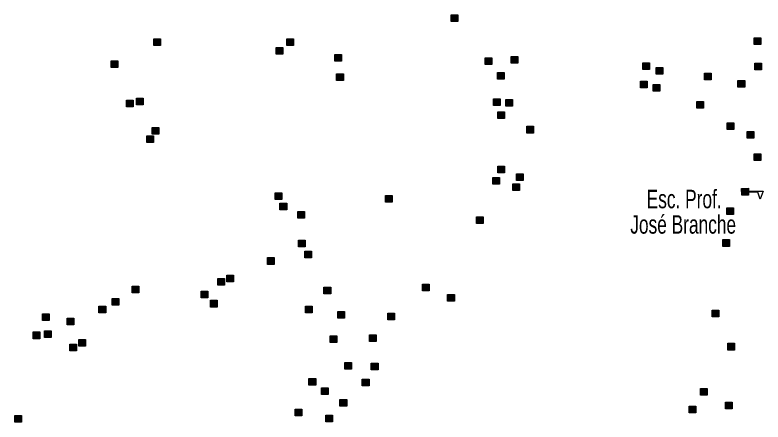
# Model space of a CAD drawing. Extents: x 649.2 to 674.4, y 7040 to 7068.1.
# Drawn here: x 670.821 to 674.06, y 7041.775 to 7043.538 of the extents above; entities that cross this region are included whole.
import ezdxf
from ezdxf.enums import TextEntityAlignment as Align

# ---------------------------------------------------------------- set-up
doc = ezdxf.new("R2010")
doc.units = 0
doc.header["$LTSCALE"] = 0.032
doc.layers.add('2', color=7, linetype='Continuous', lineweight=25)
doc.layers.add('4', color=7, linetype='Continuous', lineweight=25)
doc.layers.add('61', color=7, linetype='Continuous')

msp = doc.modelspace()

# ---------------------------------------------------------------- hatches: boundary and pattern name
at = {"layer": '2'}
for points in [[(672.7097, 7043.5383), (672.7387, 7043.5383), (672.7387, 7043.5093), (672.7097, 7043.5093)], [(671.4226, 7043.4348), (671.4516, 7043.4348), (671.4516, 7043.4058), (671.4226, 7043.4058)], [(671.9981, 7043.435), (672.0271, 7043.435), (672.0271, 7043.406), (671.9981, 7043.406)], [(674.0212, 7043.4393), (674.0502, 7043.4393), (674.0502, 7043.4103), (674.0212, 7043.4103)], [(671.9518, 7043.398), (671.9808, 7043.398), (671.9808, 7043.369), (671.9518, 7043.369)], [(671.2371, 7043.3401), (671.2661, 7043.3401), (671.2661, 7043.3111), (671.2371, 7043.3111)], [(672.2062, 7043.3664), (672.2352, 7043.3664), (672.2352, 7043.3374), (672.2062, 7043.3374)], [(672.8572, 7043.3529), (672.8862, 7043.3529), (672.8862, 7043.3239), (672.8572, 7043.3239)], [(672.9688, 7043.3579), (672.9978, 7043.3579), (672.9978, 7043.3289), (672.9688, 7043.3289)], [(673.5395, 7043.3313), (673.5685, 7043.3313), (673.5685, 7043.3023), (673.5395, 7043.3023)], [(673.5968, 7043.3104), (673.6258, 7043.3104), (673.6258, 7043.2814), (673.5968, 7043.2814)], [(674.0241, 7043.329), (674.0531, 7043.329), (674.0531, 7043.3), (674.0241, 7043.3)], [(672.2139, 7043.2832), (672.2429, 7043.2832), (672.2429, 7043.2542), (672.2139, 7043.2542)], [(672.91, 7043.2891), (672.939, 7043.2891), (672.939, 7043.2601), (672.91, 7043.2601)], [(673.8065, 7043.2867), (673.8355, 7043.2867), (673.8355, 7043.2577), (673.8065, 7043.2577)], [(673.5295, 7043.2513), (673.5585, 7043.2513), (673.5585, 7043.2223), (673.5295, 7043.2223)], [(673.9511, 7043.2538), (673.9801, 7043.2538), (673.9801, 7043.2248), (673.9511, 7043.2248)], [(673.5841, 7043.2376), (673.6131, 7043.2376), (673.6131, 7043.2086), (673.5841, 7043.2086)], [(671.3473, 7043.178), (671.3763, 7043.178), (671.3763, 7043.149), (671.3473, 7043.149)], [(672.8921, 7043.1755), (672.9211, 7043.1755), (672.9211, 7043.1465), (672.8921, 7043.1465)], [(671.3046, 7043.1689), (671.3336, 7043.1689), (671.3336, 7043.1399), (671.3046, 7043.1399)], [(672.9459, 7043.1725), (672.9749, 7043.1725), (672.9749, 7043.1435), (672.9459, 7043.1435)], [(673.7724, 7043.1639), (673.8014, 7043.1639), (673.8014, 7043.1349), (673.7724, 7043.1349)], [(672.912, 7043.1187), (672.941, 7043.1187), (672.941, 7043.0897), (672.912, 7043.0897)], [(671.4148, 7043.0509), (671.4438, 7043.0509), (671.4438, 7043.0219), (671.4148, 7043.0219)], [(673.0376, 7043.0559), (673.0666, 7043.0559), (673.0666, 7043.0269), (673.0376, 7043.0269)], [(673.9043, 7043.0711), (673.9333, 7043.0711), (673.9333, 7043.0421), (673.9043, 7043.0421)], [(671.3927, 7043.0146), (671.4217, 7043.0146), (671.4217, 7042.9856), (671.3927, 7042.9856)], [(673.9908, 7043.0338), (674.0198, 7043.0338), (674.0198, 7043.0048), (673.9908, 7043.0048)], [(674.0208, 7042.9365), (674.0498, 7042.9365), (674.0498, 7042.9075), (674.0208, 7042.9075)], [(672.9115, 7042.8828), (672.9405, 7042.8828), (672.9405, 7042.8538), (672.9115, 7042.8538)], [(672.9917, 7042.8495), (673.0207, 7042.8495), (673.0207, 7042.8205), (672.9917, 7042.8205)], [(672.89, 7042.8344), (672.919, 7042.8344), (672.919, 7042.8054), (672.89, 7042.8054)], [(672.9766, 7042.8066), (673.0056, 7042.8066), (673.0056, 7042.7776), (672.9766, 7042.7776)], [(671.9474, 7042.7676), (671.9764, 7042.7676), (671.9764, 7042.7386), (671.9474, 7042.7386)], [(672.4252, 7042.7569), (672.4542, 7042.7569), (672.4542, 7042.7279), (672.4252, 7042.7279)], [(671.9685, 7042.7229), (671.9975, 7042.7229), (671.9975, 7042.6939), (671.9685, 7042.6939)], [(672.0456, 7042.6873), (672.0746, 7042.6873), (672.0746, 7042.6583), (672.0456, 7042.6583)], [(673.9027, 7042.7025), (673.9317, 7042.7025), (673.9317, 7042.6735), (673.9027, 7042.6735)], [(672.8194, 7042.6637), (672.8484, 7042.6637), (672.8484, 7042.6347), (672.8194, 7042.6347)], [(672.048, 7042.5631), (672.077, 7042.5631), (672.077, 7042.5341), (672.048, 7042.5341)], [(673.8853, 7042.5649), (673.9143, 7042.5649), (673.9143, 7042.5359), (673.8853, 7042.5359)], [(672.0764, 7042.5153), (672.1054, 7042.5153), (672.1054, 7042.4863), (672.0764, 7042.4863)], [(671.914, 7042.487), (671.943, 7042.487), (671.943, 7042.458), (671.914, 7042.458)], [(671.6992, 7042.3964), (671.7282, 7042.3964), (671.7282, 7042.3674), (671.6992, 7042.3674)], [(671.7381, 7042.4105), (671.7671, 7042.4105), (671.7671, 7042.3815), (671.7381, 7042.3815)], [(671.328, 7042.3635), (671.357, 7042.3635), (671.357, 7042.3345), (671.328, 7042.3345)], [(672.5856, 7042.3716), (672.6146, 7042.3716), (672.6146, 7042.3426), (672.5856, 7042.3426)], [(671.6278, 7042.3416), (671.6568, 7042.3416), (671.6568, 7042.3126), (671.6278, 7042.3126)], [(672.159, 7042.3585), (672.188, 7042.3585), (672.188, 7042.3295), (672.159, 7042.3295)], [(671.2422, 7042.3095), (671.2712, 7042.3095), (671.2712, 7042.2805), (671.2422, 7042.2805)], [(671.6673, 7042.3021), (671.6963, 7042.3021), (671.6963, 7042.2731), (671.6673, 7042.2731)], [(672.6944, 7042.327), (672.7234, 7042.327), (672.7234, 7042.298), (672.6944, 7042.298)], [(671.185, 7042.2768), (671.214, 7042.2768), (671.214, 7042.2478), (671.185, 7042.2478)], [(672.0785, 7042.2772), (672.1075, 7042.2772), (672.1075, 7042.2482), (672.0785, 7042.2482)], [(670.9406, 7042.2442), (670.9696, 7042.2442), (670.9696, 7042.2152), (670.9406, 7042.2152)], [(672.2183, 7042.2537), (672.2473, 7042.2537), (672.2473, 7042.2247), (672.2183, 7042.2247)], [(672.4353, 7042.2463), (672.4643, 7042.2463), (672.4643, 7042.2173), (672.4353, 7042.2173)], [(673.839, 7042.2592), (673.868, 7042.2592), (673.868, 7042.2302), (673.839, 7042.2302)], [(671.0469, 7042.2254), (671.0759, 7042.2254), (671.0759, 7042.1964), (671.0469, 7042.1964)], [(670.9488, 7042.1698), (670.9778, 7042.1698), (670.9778, 7042.1408), (670.9488, 7042.1408)], [(670.9006, 7042.1649), (670.9296, 7042.1649), (670.9296, 7042.1359), (670.9006, 7042.1359)], [(672.1859, 7042.1489), (672.2149, 7042.1489), (672.2149, 7042.1199), (672.1859, 7042.1199)], [(672.3565, 7042.1526), (672.3855, 7042.1526), (672.3855, 7042.1236), (672.3565, 7042.1236)], [(671.0583, 7042.1118), (671.0873, 7042.1118), (671.0873, 7042.0828), (671.0583, 7042.0828)], [(671.0975, 7042.133), (671.1265, 7042.133), (671.1265, 7042.104), (671.0975, 7042.104)], [(673.9074, 7042.1159), (673.9364, 7042.1159), (673.9364, 7042.0869), (673.9074, 7042.0869)], [(672.2498, 7042.033), (672.2788, 7042.033), (672.2788, 7042.004), (672.2498, 7042.004)], [(672.3639, 7042.0293), (672.3929, 7042.0293), (672.3929, 7042.0003), (672.3639, 7042.0003)], [(672.0941, 7041.9635), (672.1231, 7041.9635), (672.1231, 7041.9345), (672.0941, 7041.9345)], [(672.3249, 7041.9607), (672.3539, 7041.9607), (672.3539, 7041.9317), (672.3249, 7041.9317)], [(672.1478, 7041.9236), (672.1768, 7041.9236), (672.1768, 7041.8946), (672.1478, 7041.8946)], [(673.7883, 7041.9201), (673.8173, 7041.9201), (673.8173, 7041.8911), (673.7883, 7041.8911)], [(672.2282, 7041.8723), (672.2572, 7041.8723), (672.2572, 7041.8433), (672.2282, 7041.8433)], [(673.8968, 7041.8614), (673.9258, 7041.8614), (673.9258, 7041.8324), (673.8968, 7041.8324)], [(672.0347, 7041.8306), (672.0637, 7041.8306), (672.0637, 7041.8016), (672.0347, 7041.8016)], [(673.7395, 7041.8433), (673.7685, 7041.8433), (673.7685, 7041.8143), (673.7395, 7041.8143)], [(670.8213, 7041.8038), (670.8503, 7041.8038), (670.8503, 7041.7748), (670.8213, 7041.7748)], [(672.1674, 7041.8045), (672.1964, 7041.8045), (672.1964, 7041.7755), (672.1674, 7041.7755)]]:
    msp.add_hatch(color=256, dxfattribs=at).paths.add_polyline_path(points)
at = {"layer": '4'}
msp.add_hatch(color=256, dxfattribs=at).paths.add_polyline_path([(673.967, 7042.7871), (673.997, 7042.7874), (673.9972, 7042.7574), (673.9672, 7042.7571)])

# ---------------------------------------------------------------- linework, layer by layer
at = {"layer": '2'}
for points in [[(672.7097, 7043.5383), (672.7387, 7043.5383), (672.7387, 7043.5093), (672.7097, 7043.5093)], [(671.4226, 7043.4348), (671.4516, 7043.4348), (671.4516, 7043.4058), (671.4226, 7043.4058)], [(671.9981, 7043.435), (672.0271, 7043.435), (672.0271, 7043.406), (671.9981, 7043.406)], [(674.0212, 7043.4393), (674.0502, 7043.4393), (674.0502, 7043.4103), (674.0212, 7043.4103)], [(671.9518, 7043.398), (671.9808, 7043.398), (671.9808, 7043.369), (671.9518, 7043.369)], [(671.2371, 7043.3401), (671.2661, 7043.3401), (671.2661, 7043.3111), (671.2371, 7043.3111)], [(672.2062, 7043.3664), (672.2352, 7043.3664), (672.2352, 7043.3374), (672.2062, 7043.3374)], [(672.8572, 7043.3529), (672.8862, 7043.3529), (672.8862, 7043.3239), (672.8572, 7043.3239)], [(672.9688, 7043.3579), (672.9978, 7043.3579), (672.9978, 7043.3289), (672.9688, 7043.3289)], [(673.5395, 7043.3313), (673.5685, 7043.3313), (673.5685, 7043.3023), (673.5395, 7043.3023)], [(673.5968, 7043.3104), (673.6258, 7043.3104), (673.6258, 7043.2814), (673.5968, 7043.2814)], [(674.0241, 7043.329), (674.0531, 7043.329), (674.0531, 7043.3), (674.0241, 7043.3)], [(672.2139, 7043.2832), (672.2429, 7043.2832), (672.2429, 7043.2542), (672.2139, 7043.2542)], [(672.91, 7043.2891), (672.939, 7043.2891), (672.939, 7043.2601), (672.91, 7043.2601)], [(673.8065, 7043.2867), (673.8355, 7043.2867), (673.8355, 7043.2577), (673.8065, 7043.2577)], [(673.5295, 7043.2513), (673.5585, 7043.2513), (673.5585, 7043.2223), (673.5295, 7043.2223)], [(673.9511, 7043.2538), (673.9801, 7043.2538), (673.9801, 7043.2248), (673.9511, 7043.2248)], [(673.5841, 7043.2376), (673.6131, 7043.2376), (673.6131, 7043.2086), (673.5841, 7043.2086)], [(671.3473, 7043.178), (671.3763, 7043.178), (671.3763, 7043.149), (671.3473, 7043.149)], [(672.8921, 7043.1755), (672.9211, 7043.1755), (672.9211, 7043.1465), (672.8921, 7043.1465)], [(671.3046, 7043.1689), (671.3336, 7043.1689), (671.3336, 7043.1399), (671.3046, 7043.1399)], [(672.9459, 7043.1725), (672.9749, 7043.1725), (672.9749, 7043.1435), (672.9459, 7043.1435)], [(673.7724, 7043.1639), (673.8014, 7043.1639), (673.8014, 7043.1349), (673.7724, 7043.1349)], [(672.912, 7043.1187), (672.941, 7043.1187), (672.941, 7043.0897), (672.912, 7043.0897)], [(671.4148, 7043.0509), (671.4438, 7043.0509), (671.4438, 7043.0219), (671.4148, 7043.0219)], [(673.0376, 7043.0559), (673.0666, 7043.0559), (673.0666, 7043.0269), (673.0376, 7043.0269)], [(673.9043, 7043.0711), (673.9333, 7043.0711), (673.9333, 7043.0421), (673.9043, 7043.0421)], [(671.3927, 7043.0146), (671.4217, 7043.0146), (671.4217, 7042.9856), (671.3927, 7042.9856)], [(673.9908, 7043.0338), (674.0198, 7043.0338), (674.0198, 7043.0048), (673.9908, 7043.0048)], [(674.0208, 7042.9365), (674.0498, 7042.9365), (674.0498, 7042.9075), (674.0208, 7042.9075)], [(672.9115, 7042.8828), (672.9405, 7042.8828), (672.9405, 7042.8538), (672.9115, 7042.8538)], [(672.9917, 7042.8495), (673.0207, 7042.8495), (673.0207, 7042.8205), (672.9917, 7042.8205)], [(672.89, 7042.8344), (672.919, 7042.8344), (672.919, 7042.8054), (672.89, 7042.8054)], [(672.9766, 7042.8066), (673.0056, 7042.8066), (673.0056, 7042.7776), (672.9766, 7042.7776)], [(671.9474, 7042.7676), (671.9764, 7042.7676), (671.9764, 7042.7386), (671.9474, 7042.7386)], [(672.4252, 7042.7569), (672.4542, 7042.7569), (672.4542, 7042.7279), (672.4252, 7042.7279)], [(671.9685, 7042.7229), (671.9975, 7042.7229), (671.9975, 7042.6939), (671.9685, 7042.6939)], [(672.0456, 7042.6873), (672.0746, 7042.6873), (672.0746, 7042.6583), (672.0456, 7042.6583)], [(673.9027, 7042.7025), (673.9317, 7042.7025), (673.9317, 7042.6735), (673.9027, 7042.6735)], [(672.8194, 7042.6637), (672.8484, 7042.6637), (672.8484, 7042.6347), (672.8194, 7042.6347)], [(672.048, 7042.5631), (672.077, 7042.5631), (672.077, 7042.5341), (672.048, 7042.5341)], [(673.8853, 7042.5649), (673.9143, 7042.5649), (673.9143, 7042.5359), (673.8853, 7042.5359)], [(672.0764, 7042.5153), (672.1054, 7042.5153), (672.1054, 7042.4863), (672.0764, 7042.4863)], [(671.914, 7042.487), (671.943, 7042.487), (671.943, 7042.458), (671.914, 7042.458)], [(671.6992, 7042.3964), (671.7282, 7042.3964), (671.7282, 7042.3674), (671.6992, 7042.3674)], [(671.7381, 7042.4105), (671.7671, 7042.4105), (671.7671, 7042.3815), (671.7381, 7042.3815)], [(671.328, 7042.3635), (671.357, 7042.3635), (671.357, 7042.3345), (671.328, 7042.3345)], [(672.5856, 7042.3716), (672.6146, 7042.3716), (672.6146, 7042.3426), (672.5856, 7042.3426)], [(671.6278, 7042.3416), (671.6568, 7042.3416), (671.6568, 7042.3126), (671.6278, 7042.3126)], [(672.159, 7042.3585), (672.188, 7042.3585), (672.188, 7042.3295), (672.159, 7042.3295)], [(671.2422, 7042.3095), (671.2712, 7042.3095), (671.2712, 7042.2805), (671.2422, 7042.2805)], [(671.6673, 7042.3021), (671.6963, 7042.3021), (671.6963, 7042.2731), (671.6673, 7042.2731)], [(672.6944, 7042.327), (672.7234, 7042.327), (672.7234, 7042.298), (672.6944, 7042.298)], [(671.185, 7042.2768), (671.214, 7042.2768), (671.214, 7042.2478), (671.185, 7042.2478)], [(672.0785, 7042.2772), (672.1075, 7042.2772), (672.1075, 7042.2482), (672.0785, 7042.2482)], [(670.9406, 7042.2442), (670.9696, 7042.2442), (670.9696, 7042.2152), (670.9406, 7042.2152)], [(672.2183, 7042.2537), (672.2473, 7042.2537), (672.2473, 7042.2247), (672.2183, 7042.2247)], [(672.4353, 7042.2463), (672.4643, 7042.2463), (672.4643, 7042.2173), (672.4353, 7042.2173)], [(673.839, 7042.2592), (673.868, 7042.2592), (673.868, 7042.2302), (673.839, 7042.2302)], [(671.0469, 7042.2254), (671.0759, 7042.2254), (671.0759, 7042.1964), (671.0469, 7042.1964)], [(670.9488, 7042.1698), (670.9778, 7042.1698), (670.9778, 7042.1408), (670.9488, 7042.1408)], [(670.9006, 7042.1649), (670.9296, 7042.1649), (670.9296, 7042.1359), (670.9006, 7042.1359)], [(672.1859, 7042.1489), (672.2149, 7042.1489), (672.2149, 7042.1199), (672.1859, 7042.1199)], [(672.3565, 7042.1526), (672.3855, 7042.1526), (672.3855, 7042.1236), (672.3565, 7042.1236)], [(671.0583, 7042.1118), (671.0873, 7042.1118), (671.0873, 7042.0828), (671.0583, 7042.0828)], [(671.0975, 7042.133), (671.1265, 7042.133), (671.1265, 7042.104), (671.0975, 7042.104)], [(673.9074, 7042.1159), (673.9364, 7042.1159), (673.9364, 7042.0869), (673.9074, 7042.0869)], [(672.2498, 7042.033), (672.2788, 7042.033), (672.2788, 7042.004), (672.2498, 7042.004)], [(672.3639, 7042.0293), (672.3929, 7042.0293), (672.3929, 7042.0003), (672.3639, 7042.0003)], [(672.0941, 7041.9635), (672.1231, 7041.9635), (672.1231, 7041.9345), (672.0941, 7041.9345)], [(672.3249, 7041.9607), (672.3539, 7041.9607), (672.3539, 7041.9317), (672.3249, 7041.9317)], [(672.1478, 7041.9236), (672.1768, 7041.9236), (672.1768, 7041.8946), (672.1478, 7041.8946)], [(673.7883, 7041.9201), (673.8173, 7041.9201), (673.8173, 7041.8911), (673.7883, 7041.8911)], [(672.2282, 7041.8723), (672.2572, 7041.8723), (672.2572, 7041.8433), (672.2282, 7041.8433)], [(673.8968, 7041.8614), (673.9258, 7041.8614), (673.9258, 7041.8324), (673.8968, 7041.8324)], [(672.0347, 7041.8306), (672.0637, 7041.8306), (672.0637, 7041.8016), (672.0347, 7041.8016)], [(673.7395, 7041.8433), (673.7685, 7041.8433), (673.7685, 7041.8143), (673.7395, 7041.8143)], [(670.8213, 7041.8038), (670.8503, 7041.8038), (670.8503, 7041.7748), (670.8213, 7041.7748)], [(672.1674, 7041.8045), (672.1964, 7041.8045), (672.1964, 7041.7755), (672.1674, 7041.7755)]]:
    msp.add_lwpolyline(points, close=True, dxfattribs=at)
at = {"layer": '4'}
msp.add_line((673.9971, 7042.7749), (673.9971, 7042.7699), dxfattribs=at)
for points in [[(673.967, 7042.7871), (673.997, 7042.7874), (673.9972, 7042.7574), (673.9672, 7042.7571)], [(673.9971, 7042.7749), (674.0596, 7042.7754), (674.0474, 7042.7403), (674.0366, 7042.7702), (673.9971, 7042.7699)]]:
    msp.add_lwpolyline(points, close=True, dxfattribs=at)

# ---------------------------------------------------------------- texts
at = {"layer": '61', "width": 0.7}
for s, p in [('  Esc. Prof.   ', (673.9429, 7042.7009)), ('José Branche', (673.9429, 7042.5909))]:
    msp.add_text(s, height=0.08, dxfattribs=at).set_placement(p, align=Align.RIGHT)

doc.saveas('drawing.dxf')
